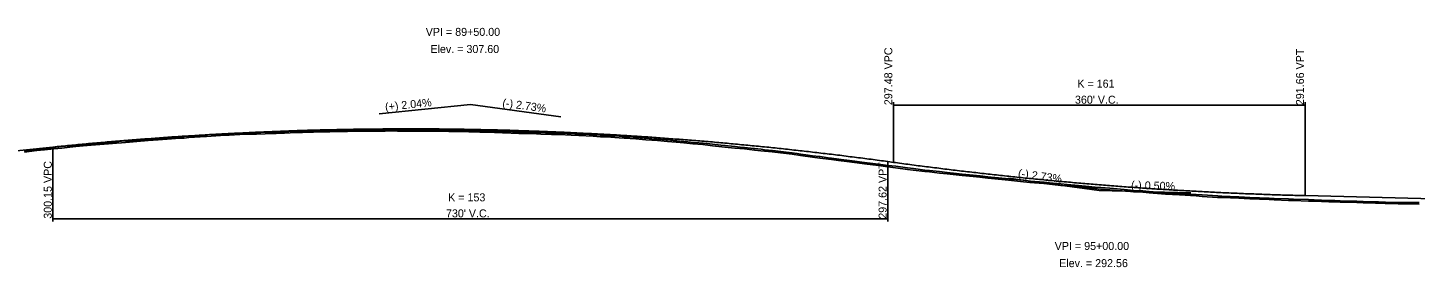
# Model space of a CAD drawing. Extents: x 1876258 to 1932803, y 754739 to 837911.
# Drawn here: x 1886926 to 1888139, y 831400 to 831609 of the extents above; entities that cross this region are included whole.
import ezdxf

# ---------------------------------------------------------------- set-up
doc = ezdxf.new("R2010")
doc.units = 0
for name, color, linetype in [('RD_DDB_GradeTX', 7, 'Continuous'), ('RD_DDB_Profile_EX', 7, 'Continuous'), ('RD_DDB_Profile_Lbl', 7, 'Continuous'), ('RD_DDB_Profile_PR', 7, 'Continuous'), ('RD_DDB_StripGrade', 7, 'Continuous'), ('RD_DDB_VCLbl', 7, 'Continuous'), ('RD_Sketch1', 7, 'Continuous')]:
    doc.layers.add(name, color=color, linetype=linetype)

msp = doc.modelspace()

# ---------------------------------------------------------------- linework, layer by layer
at = {"layer": 'RD_DDB_GradeTX'}
for p, q in [((1887233.5, 831534.2), (1887313.1, 831542.3)), ((1887392.3, 831531.5), (1887313.1, 831542.3)), ((1887783.8, 831477.9), (1887863.1, 831467.1)), ((1887943.1, 831465.1), (1887863.1, 831467.1))]:
    msp.add_line(p, q, dxfattribs=at)
at = {"layer": 'RD_DDB_Profile_EX'}
for points in [[(1886923.1, 831500.7), (1886927.4, 831501.2), (1886934, 831502), (1886940.6, 831502.7), (1886948.9, 831503.5), (1886955.8, 831504.2), (1886962.8, 831505), (1886968.2, 831505.5), (1886974.5, 831506.1), (1886981.6, 831506.8), (1886989.1, 831507.3), (1886996.7, 831507.9), (1887003.8, 831508.4), (1887008.2, 831508.9), (1887015.1, 831509.3), (1887021.4, 831509.8)], [(1887021.4, 831509.8), (1887031.3, 831510.7), (1887040.1, 831511.4), (1887048, 831511.9), (1887059.2, 831512.8), (1887062.9, 831513), (1887067, 831513.3), (1887076.8, 831514), (1887082.4, 831514.4), (1887094.6, 831515.1), (1887102.1, 831515.5), (1887111.4, 831516), (1887118.9, 831516.3), (1887126.1, 831516.4), (1887133.8, 831516.7), (1887143.4, 831517), (1887150.5, 831517.3), (1887160.5, 831517.7), (1887166.2, 831517.9), (1887176, 831518.2), (1887183, 831518.3), (1887190.3, 831518.5), (1887198.6, 831518.7), (1887205.6, 831518.8), (1887212.8, 831518.9), (1887221.4, 831519), (1887228.5, 831519.1), (1887238.6, 831519.1), (1887243.3, 831519.2), (1887249.5, 831519.1), (1887254.4, 831519.1), (1887261.6, 831519.1), (1887266.4, 831519.1), (1887274.9, 831519.1), (1887282, 831519), (1887288.9, 831518.9), (1887294.2, 831518.8), (1887304.4, 831518.7), (1887311.7, 831518.4), (1887321.4, 831518.1), (1887326.5, 831518), (1887334.1, 831517.8), (1887341.1, 831517.6), (1887348.7, 831517.3), (1887355.6, 831517), (1887362.4, 831516.8), (1887370.9, 831516.6), (1887374.8, 831516.4), (1887384, 831516.2), (1887391.1, 831516.1), (1887401.4, 831515.5), (1887408, 831515.2), (1887420.4, 831514.6), (1887427, 831514.1), (1887432.1, 831513.9), (1887443.1, 831513.2), (1887447.6, 831512.9), (1887457.8, 831512.2), (1887466.7, 831511.5), (1887476.7, 831510.7), (1887485.4, 831510), (1887493.1, 831509.4), (1887499.8, 831508.7), (1887507.8, 831507.9), (1887516.5, 831507.2), (1887524.8, 831506.3), (1887535.7, 831505.1), (1887544.4, 831504.2), (1887552.7, 831503.4), (1887561.5, 831502.4), (1887567.2, 831501.8), (1887577.1, 831500.8), (1887584.4, 831500), (1887594.4, 831498.8), (1887601.8, 831497.7), (1887612.3, 831496.3), (1887618.7, 831495.5), (1887628.8, 831494.1), (1887635.1, 831493.4), (1887644.6, 831492.1), (1887646.7, 831491.8), (1887649, 831491.6), (1887653.3, 831491), (1887657.7, 831490.4), (1887665.1, 831489.5), (1887670, 831488.9), (1887678.2, 831487.8), (1887684.9, 831487), (1887695.4, 831485.6), (1887700.4, 831485), (1887710.5, 831483.8), (1887714.6, 831483.4), (1887723.3, 831482.4), (1887730.1, 831481.6), (1887737.9, 831480.8), (1887743.1, 831480.2), (1887752.7, 831479.3), (1887758.6, 831478.7), (1887765.5, 831477.9), (1887771.7, 831477.3), (1887780.9, 831476.3)], [(1887780.9, 831476.3), (1887786.3, 831475.7), (1887796.8, 831474.7), (1887802.4, 831474.2), (1887806.5, 831473.9), (1887814.7, 831473.1), (1887819.5, 831472.6), (1887829.4, 831471.6), (1887834.9, 831471.1), (1887844.8, 831470.3), (1887851, 831469.7), (1887859.2, 831468.9), (1887864.2, 831468.4), (1887872.3, 831467.7), (1887878.5, 831467.2), (1887887.7, 831466.4), (1887892.9, 831466), (1887901.2, 831465.5), (1887906.6, 831465), (1887921, 831464), (1887927.2, 831463.6), (1887933.1, 831463.2), (1887947.7, 831462.3), (1887953, 831462), (1887966.5, 831461.1), (1887970.2, 831460.9), (1887985, 831460.3), (1887989.9, 831460.1), (1887994.6, 831459.8), (1888011.5, 831459.1), (1888016.1, 831459), (1888028.4, 831458.5), (1888032.9, 831458.3), (1888046, 831457.9), (1888051.1, 831457.7), (1888063.7, 831457.3), (1888069, 831457.1), (1888073.8, 831457), (1888088.2, 831456.5), (1888093.8, 831456.3), (1888104.6, 831456), (1888107.3, 831455.9), (1888113.2, 831455.8), (1888124.4, 831455.4), (1888136.5, 831455.3), (1888142.8, 831455.2)]]:
    msp.add_lwpolyline(points, dxfattribs=at)
at = {"layer": 'RD_DDB_Profile_PR'}
for p, q in [((1886841, 831494.1), (1886948.1, 831505.1)), ((1887678.1, 831492.4), (1887683.1, 831491.7)), ((1888043.1, 831462.6), (1888558.1, 831449.7))]:
    msp.add_line(p, q, dxfattribs=at)
for points in [[(1886948.1, 831505.1), (1886962.7, 831506.5), (1886977.3, 831507.9), (1886991.9, 831509.2), (1887006.5, 831510.5), (1887021.1, 831511.6), (1887035.7, 831512.7), (1887050.3, 831513.8), (1887064.9, 831514.7), (1887079.5, 831515.6), (1887094.1, 831516.5), (1887108.7, 831517.2), (1887123.3, 831517.9), (1887137.9, 831518.5), (1887152.5, 831519.1), (1887167.1, 831519.6), (1887181.7, 831520), (1887196.3, 831520.3), (1887210.9, 831520.6), (1887225.5, 831520.8), (1887240.1, 831520.9), (1887254.7, 831521), (1887269.3, 831521), (1887283.9, 831520.9), (1887298.5, 831520.7), (1887313.1, 831520.5), (1887327.7, 831520.2), (1887342.3, 831519.9), (1887356.9, 831519.4), (1887371.5, 831518.9), (1887386.1, 831518.4), (1887400.7, 831517.7), (1887415.3, 831517), (1887429.9, 831516.3), (1887444.5, 831515.4), (1887459.1, 831514.5), (1887473.7, 831513.5), (1887488.3, 831512.4), (1887502.9, 831511.3), (1887517.5, 831510.1), (1887532.1, 831508.9), (1887546.7, 831507.5), (1887561.3, 831506.1), (1887575.9, 831504.7), (1887590.5, 831503.1), (1887605.1, 831501.5), (1887619.7, 831499.8), (1887634.3, 831498.1), (1887648.9, 831496.2), (1887663.5, 831494.4), (1887678.1, 831492.4)], [(1887683.1, 831491.7), (1887690.3, 831490.7), (1887697.5, 831489.8), (1887704.7, 831488.8), (1887711.9, 831487.9), (1887719.1, 831487), (1887726.3, 831486.1), (1887733.5, 831485.2), (1887740.7, 831484.3), (1887747.9, 831483.5), (1887755.1, 831482.7), (1887762.3, 831481.9), (1887769.5, 831481.1), (1887776.7, 831480.3), (1887783.9, 831479.5), (1887791.1, 831478.8), (1887798.3, 831478), (1887805.5, 831477.3), (1887812.7, 831476.6), (1887819.9, 831475.9), (1887827.1, 831475.2), (1887834.3, 831474.6), (1887841.5, 831473.9), (1887848.7, 831473.3), (1887855.9, 831472.7), (1887863.1, 831472.1), (1887870.3, 831471.5), (1887877.5, 831471), (1887884.7, 831470.4), (1887891.9, 831469.9), (1887899.1, 831469.4), (1887906.3, 831468.9), (1887913.5, 831468.4), (1887920.7, 831468), (1887927.9, 831467.5), (1887935.1, 831467.1), (1887942.3, 831466.7), (1887949.5, 831466.3), (1887956.7, 831465.9), (1887963.9, 831465.5), (1887971.1, 831465.2), (1887978.3, 831464.9), (1887985.5, 831464.6), (1887992.7, 831464.2), (1887999.9, 831464), (1888007.1, 831463.7), (1888014.3, 831463.4), (1888021.5, 831463.2), (1888028.7, 831463), (1888035.9, 831462.8), (1888043.1, 831462.6)]]:
    msp.add_spline(points, degree=3, dxfattribs=at)
at = {"layer": 'RD_DDB_VCLbl'}
for p, q in [((1887683.1, 831544.2), (1887683.1, 831491.7)), ((1887683.1, 831541.7), (1888043.1, 831541.7)), ((1888043.1, 831544.2), (1888043.1, 831462.6)), ((1886948.1, 831439.9), (1886948.1, 831505.1)), ((1887678.1, 831439.9), (1887678.1, 831492.4)), ((1886948.1, 831442.4), (1887678.1, 831442.4))]:
    msp.add_line(p, q, dxfattribs=at)
at = {"layer": 'RD_Sketch1'}
msp.add_lwpolyline([(1886923, 831501.9), (1886927.3, 831502.5), (1886933.9, 831503.2), (1886940.4, 831503.9), (1886948.7, 831504.8), (1886955.7, 831505.5), (1886962.7, 831506.2), (1886968.1, 831506.7), (1886974.3, 831507.4), (1886981.5, 831508), (1886989, 831508.5), (1886996.6, 831509.1), (1887003.7, 831509.7), (1887008.1, 831510.1), (1887015, 831510.5), (1887021.2, 831511), (1887031.2, 831512), (1887040, 831512.6), (1887047.9, 831513.2), (1887059.1, 831514.1), (1887062.8, 831514.3), (1887066.9, 831514.5), (1887072.4, 831514.9), (1887076.7, 831515.3), (1887081.9, 831515.6), (1887082.3, 831515.7), (1887091.5, 831516.2), (1887094.5, 831516.3), (1887101.1, 831516.7), (1887102, 831516.7), (1887110.7, 831517.2), (1887111.3, 831517.2), (1887118.9, 831517.6), (1887120.3, 831517.6), (1887126.1, 831517.7), (1887129.8, 831517.8), (1887133.7, 831518), (1887139.4, 831518.1), (1887143.4, 831518.2), (1887149, 831518.4), (1887150.4, 831518.5), (1887158.5, 831518.9), (1887160.4, 831518.9), (1887166.1, 831519.1), (1887168.1, 831519.2), (1887176, 831519.4), (1887177.7, 831519.5), (1887183, 831519.6), (1887187.3, 831519.7), (1887190.3, 831519.7), (1887196.8, 831519.9), (1887198.5, 831519.9), (1887205.6, 831520.1), (1887206.4, 831520.1), (1887212.8, 831520.1), (1887216, 831520.2), (1887221.4, 831520.2), (1887225.6, 831520.3), (1887228.5, 831520.3), (1887235.2, 831520.4), (1887238.6, 831520.4), (1887243.3, 831520.4), (1887244.7, 831520.4), (1887249.5, 831520.4), (1887254.3, 831520.4), (1887254.4, 831520.4), (1887261.6, 831520.4), (1887263.9, 831520.4), (1887266.4, 831520.3), (1887273.4, 831520.4), (1887275, 831520.4), (1887282.1, 831520.3), (1887283, 831520.3), (1887288.9, 831520.2), (1887292.6, 831520.1), (1887294.2, 831520.1), (1887302.2, 831519.9), (1887304.5, 831519.9), (1887311.7, 831519.7), (1887311.8, 831519.7), (1887321.3, 831519.4), (1887321.4, 831519.4), (1887326.5, 831519.3), (1887330.9, 831519.2), (1887334.1, 831519.1), (1887340.5, 831518.9), (1887341.2, 831518.8), (1887348.8, 831518.6), (1887350.1, 831518.5), (1887355.6, 831518.3), (1887359.6, 831518.2), (1887362.4, 831518.1), (1887369.2, 831517.9), (1887370.9, 831517.8), (1887374.9, 831517.7), (1887378.8, 831517.6), (1887384, 831517.5), (1887388.3, 831517.4), (1887391.1, 831517.3), (1887397.9, 831517), (1887401.4, 831516.8), (1887407.5, 831516.5), (1887408, 831516.4), (1887417.1, 831516), (1887420.5, 831515.9), (1887426.7, 831515.4), (1887427.1, 831515.4), (1887432.1, 831515.1), (1887436.2, 831514.9), (1887443.2, 831514.5), (1887445.8, 831514.3), (1887447.7, 831514.1), (1887455.4, 831513.6), (1887457.9, 831513.4), (1887465, 831512.9), (1887466.8, 831512.8), (1887474.5, 831512.1), (1887476.8, 831512), (1887484.1, 831511.4), (1887485.5, 831511.3), (1887493.2, 831510.6), (1887493.7, 831510.6), (1887499.9, 831509.9), (1887503.3, 831509.6), (1887507.9, 831509.2), (1887512.8, 831508.8), (1887516.6, 831508.4), (1887522.4, 831507.8), (1887524.9, 831507.6), (1887532, 831506.8), (1887535.8, 831506.4), (1887541.6, 831505.8), (1887544.6, 831505.5), (1887551.1, 831504.8), (1887552.9, 831504.7), (1887560.7, 831503.8), (1887561.7, 831503.7), (1887567.3, 831503.1), (1887570.3, 831502.8), (1887577.2, 831502.1), (1887579.9, 831501.8), (1887584.5, 831501.2), (1887589.4, 831500.6), (1887594.6, 831500), (1887599, 831499.4), (1887602, 831499), (1887608.6, 831498.1), (1887612.4, 831497.5), (1887618.2, 831496.8), (1887618.9, 831496.7), (1887627.8, 831495.5), (1887629, 831495.3), (1887635.3, 831494.6), (1887637.3, 831494.3), (1887644.8, 831493.3), (1887646.9, 831493.1), (1887649.2, 831492.8), (1887653.4, 831492.2), (1887657.8, 831491.7), (1887665.2, 831490.8), (1887670.1, 831490.1), (1887678.3, 831489.1), (1887685.1, 831488.3), (1887695.5, 831486.9), (1887700.6, 831486.3), (1887710.6, 831485), (1887714.7, 831484.7), (1887723.4, 831483.7), (1887730.2, 831482.9), (1887738.1, 831482), (1887743.2, 831481.4), (1887752.8, 831480.5), (1887758.8, 831479.9), (1887765.6, 831479.1), (1887771.8, 831478.5), (1887781.1, 831477.6), (1887786.5, 831477), (1887797, 831476), (1887802.5, 831475.4), (1887806.6, 831475.1), (1887814.8, 831474.4), (1887819.6, 831473.9), (1887829.6, 831472.9), (1887835, 831472.3), (1887844.9, 831471.5), (1887851.1, 831470.9), (1887859.4, 831470.1), (1887864.3, 831469.7), (1887872.4, 831469), (1887878.6, 831468.5), (1887887.8, 831467.7), (1887893, 831467.2), (1887901.3, 831466.7), (1887906.7, 831466.3), (1887921.1, 831465.2), (1887927.3, 831464.9), (1887933.2, 831464.4), (1887947.8, 831463.5), (1887953.1, 831463.2), (1887966.6, 831462.4), (1887970.3, 831462.2), (1887985, 831461.5), (1887990, 831461.3), (1887994.6, 831461.1), (1888011.5, 831460.4), (1888016.1, 831460.2), (1888028.4, 831459.7), (1888033, 831459.6), (1888046.1, 831459.2), (1888051.1, 831459), (1888063.7, 831458.5), (1888069, 831458.3), (1888073.8, 831458.2), (1888088.2, 831457.8), (1888093.9, 831457.6), (1888104.6, 831457.3), (1888107.3, 831457.2), (1888113.3, 831457), (1888124.4, 831456.7), (1888136.5, 831456.5), (1888142.9, 831456.5)], dxfattribs=at)

# ---------------------------------------------------------------- texts
at = {"layer": 'RD_DDB_GradeTX'}
for s, rotation, p in [('(+) 2.04%', 5.8261, (1887238.9, 831536.7)), ('(-) 2.73%', 352.2144, (1887340.8, 831540.5)), ('(-) 2.73%', 352.2144, (1887791.7, 831478.9)), ('(-) 0.50%', 358.5679, (1887890.8, 831468.4))]:
    msp.add_text(s, height=7, rotation=rotation, dxfattribs=at).set_placement(p)
at = {"layer": 'RD_DDB_Profile_Lbl'}
for s, p in [('VPI = 89+50.00', (1887274.1, 831602.3)), ('Elev. = 307.60', (1887278.2, 831587.3)), ('VPI = 95+00.00', (1887824.1, 831415.1)), ('Elev. = 292.56', (1887828, 831400.1))]:
    msp.add_text(s, height=7, dxfattribs=at).set_placement(p)
at = {"layer": 'RD_DDB_StripGrade'}
for s, p in [('297.48 VPC', (1887682.1, 831541.7)), ('291.66 VPT', (1888042.1, 831541.7)), ('300.15 VPC', (1886947.1, 831442.4)), ('297.62 VPT', (1887677.1, 831442.4))]:
    msp.add_text(s, height=7, rotation=90, dxfattribs=at).set_placement(p)
at = {"layer": 'RD_DDB_VCLbl'}
for s, p in [('K = 161', (1887843.9, 831557)), ("360' V.C.", (1887841.8, 831543)), ('K = 153', (1887293.7, 831457.6)), ("730' V.C.", (1887291.8, 831443.6))]:
    msp.add_text(s, height=7, dxfattribs=at).set_placement(p)

doc.saveas('drawing.dxf')
